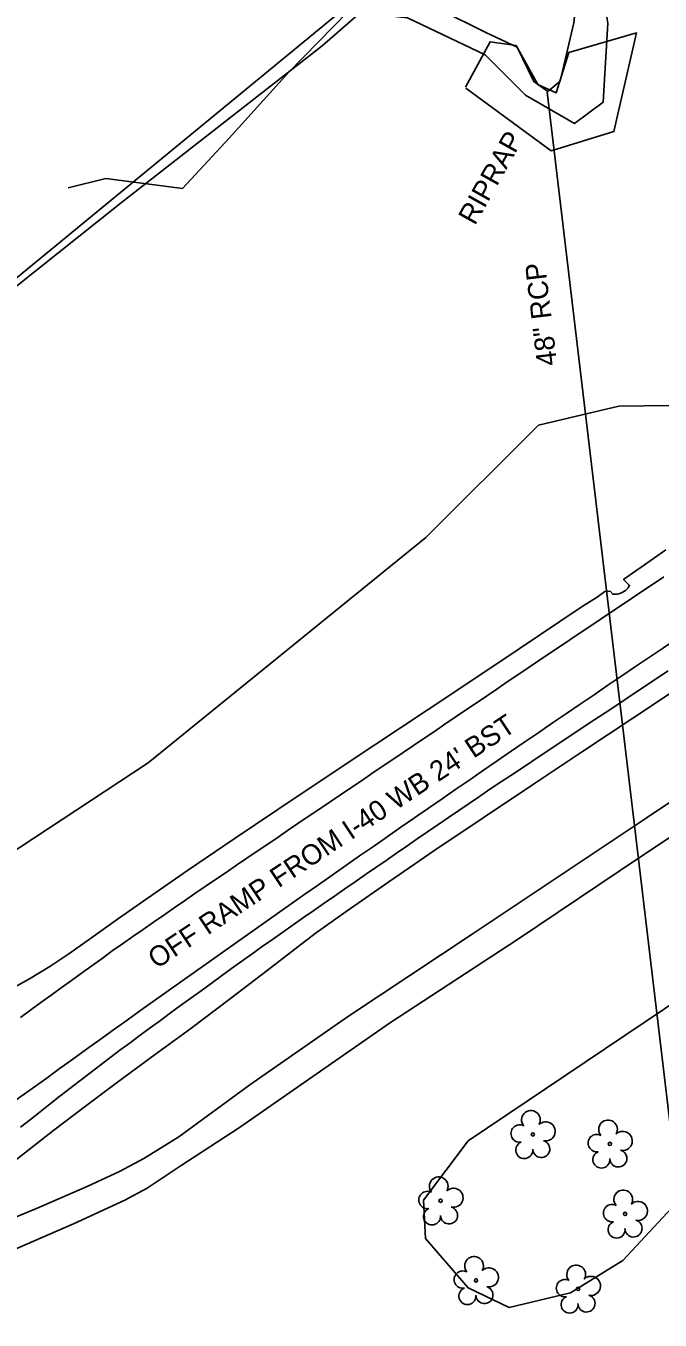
# Model space of a CAD drawing. Extents: x 2074109 to 2077820, y 741079 to 746031.
# Drawn here: x 2075438.5 to 2075564.6, y 743972 to 744229 of the extents above; entities that cross this region are included whole.
import ezdxf

# ---------------------------------------------------------------- set-up
doc = ezdxf.new("R2010")
doc.units = 0
for name, color, linetype in [('Exist Horizontal Alignment', 7, 'Continuous'), ('Exist Hydro Stream or Body of Water', 7, 'Continuous'), ('Exist Other Culture Area Outline', 7, 'Continuous'), ('Exist Other Culture Area Outline Text', 7, 'Continuous'), ('Exist Other Culture Fence Line', 7, 'Continuous'), ('Exist Right of Way Line', 7, 'Continuous'), ('Exist Roads EOP', 7, 'Continuous'), ('Exist Roads EOP Text', 7, 'Continuous'), ('Exist Roads EOT', 7, 'Continuous'), ('Exist Structure Minor Paved Ditch or Gutter', 7, 'Continuous'), ('Exist Structure Minor Pipes RCP 48 Inch', 7, 'Continuous'), ('Exist Structure Minor Pipes RCP 48 Inch Text', 7, 'Continuous'), ('Exist Vegetation Hedge Row', 7, 'Continuous'), ('Exist Vegetation Tree CELL', 7, 'Continuous'), ('Exist Vegetation Woods Line', 7, 'Continuous')]:
    doc.layers.add(name, color=color, linetype=linetype)

msp = doc.modelspace()

# ---------------------------------------------------------------- linework, layer by layer
at = {"layer": 'Exist Horizontal Alignment'}
msp.add_arc((2078143.35, 740278.32), 4614.57, 123.47052, 126.11267, dxfattribs=at)
at = {"layer": 'Exist Hydro Stream or Body of Water'}
msp.add_lwpolyline([(2075544.73, 744283.29), (2075551.12, 744265.56), (2075547.41, 744229.65), (2075544.66, 744218.04), (2075542.23, 744216.03), (2075539.46, 744217.96), (2075536.16, 744224.81), (2075529.92, 744227.74), (2075511.75, 744236.8), (2075501.32, 744236.15), (2075495.85, 744232.06)], dxfattribs=at)
at = {"layer": 'Exist Other Culture Area Outline'}
msp.add_lwpolyline([(2075525.97, 744216.67), (2075542.88, 744204.24), (2075555.36, 744208.06), (2075559.85, 744227.64), (2075546.4, 744223.74), (2075543.91, 744215.76), (2075540.23, 744217.4), (2075535.92, 744225.12), (2075530.78, 744225.9), (2075525.9, 744216.89)], dxfattribs=at)
at = {"layer": 'Exist Other Culture Fence Line'}
msp.add_lwpolyline([(2075690.21, 744385.61), (2075656.34, 744358.38), (2075632.77, 744338.73), (2075611.28, 744320.39), (2075581.11, 744296.73), (2075554.17, 744274.55), (2075497.37, 744225.11), (2075457.53, 744193.95), (2075418.99, 744163.3)], dxfattribs=at)
at = {"layer": 'Exist Right of Way Line'}
msp.add_line((2075289.65, 744058.22), (2075694.31, 744390.69), dxfattribs=at)
at = {"layer": 'Exist Roads EOP'}
for points in [[(2075434.35, 744037.03), (2075439.27, 744039.77), (2075443.28, 744042.2), (2075447.08, 744044.73), (2075451.39, 744047.77), (2075456.96, 744051.71), (2075463.48, 744056.29), (2075470.63, 744061.25), (2075479.91, 744067.58), (2075492.84, 744076.24), (2075507.84, 744086.22), (2075523.34, 744096.52), (2075536.55, 744105.3), (2075544.65, 744110.75), (2075549.26, 744113.85), (2075552.01, 744115.59), (2075553.55, 744116.67), (2075554.62, 744116.78), (2075555.16, 744116.18), (2075555.45, 744116.14), (2075555.74, 744116.13), (2075556.04, 744116.17), (2075556.36, 744116.24), (2075556.68, 744116.35), (2075557, 744116.51), (2075557.34, 744116.7), (2075557.66, 744116.91), (2075557.94, 744117.15), (2075558.17, 744117.4), (2075558.35, 744117.66), (2075558.47, 744117.9), (2075557.28, 744119.09), (2075559.73, 744120.78), (2075560.8, 744121.51), (2075565.71, 744124.93)], [(2075569.19, 744098.24), (2075559.13, 744091.55), (2075549.16, 744084.93), (2075539.16, 744078.3), (2075529.36, 744071.75), (2075519.82, 744065.31), (2075510.65, 744059.03), (2075502.16, 744053.11), (2075496.03, 744048.72), (2075491.98, 744045.64), (2075486.48, 744041.42), (2075479.18, 744035.81), (2075471.31, 744029.91), (2075463.31, 744024.04), (2075456.44, 744019), (2075450.62, 744014.68), (2075444.07, 744009.67), (2075436.71, 744003.91)]]:
    msp.add_lwpolyline(points, dxfattribs=at)
at = {"layer": 'Exist Roads EOT'}
for points in [[(2075565.29, 744119.61), (2075563.22, 744118.22), (2075561.14, 744116.83), (2075559.07, 744115.44), (2075556.99, 744114.05), (2075554.91, 744112.66), (2075552.84, 744111.27), (2075550.76, 744109.88), (2075548.69, 744108.48), (2075546.61, 744107.09), (2075544.53, 744105.7), (2075542.46, 744104.31), (2075540.39, 744102.91), (2075538.32, 744101.51), (2075536.25, 744100.11), (2075534.18, 744098.71), (2075532.11, 744097.31), (2075530.04, 744095.91), (2075527.97, 744094.51), (2075525.9, 744093.11), (2075523.83, 744091.71), (2075521.76, 744090.31), (2075519.69, 744088.91), (2075517.62, 744087.51), (2075515.56, 744086.1), (2075513.49, 744084.7), (2075511.42, 744083.3), (2075509.35, 744081.9), (2075507.28, 744080.51), (2075505.21, 744079.11), (2075503.13, 744077.71), (2075501.06, 744076.31), (2075498.99, 744074.92), (2075496.92, 744073.52), (2075494.85, 744072.12), (2075492.78, 744070.72), (2075490.71, 744069.32), (2075488.65, 744067.91), (2075486.58, 744066.51), (2075484.51, 744065.1), (2075482.44, 744063.7), (2075480.38, 744062.3), (2075478.31, 744060.89), (2075476.24, 744059.49), (2075474.18, 744058.09), (2075472.12, 744056.67), (2075470.06, 744055.25), (2075468.01, 744053.82), (2075465.96, 744052.4), (2075463.9, 744050.98), (2075461.85, 744049.56), (2075459.79, 744048.13), (2075457.74, 744046.71), (2075455.69, 744045.28), (2075453.67, 744043.81), (2075451.64, 744042.35), (2075449.61, 744040.89), (2075447.59, 744039.43), (2075445.56, 744037.97), (2075443.54, 744036.5), (2075441.52, 744035.03), (2075439.5, 744033.56), (2075437.48, 744032.09)], [(2075566.13, 744100.9), (2075564.05, 744099.51), (2075561.97, 744098.13), (2075559.89, 744096.75), (2075557.8, 744095.37), (2075555.72, 744093.99), (2075553.63, 744092.61), (2075551.55, 744091.23), (2075549.47, 744089.85), (2075547.38, 744088.47), (2075545.3, 744087.09), (2075543.22, 744085.71), (2075541.14, 744084.33), (2075539.06, 744082.94), (2075536.98, 744081.55), (2075534.9, 744080.16), (2075532.82, 744078.78), (2075530.74, 744077.39), (2075528.67, 744075.99), (2075526.61, 744074.58), (2075524.54, 744073.17), (2075522.48, 744071.77), (2075520.41, 744070.36), (2075518.35, 744068.95), (2075516.28, 744067.54), (2075514.23, 744066.12), (2075512.17, 744064.7), (2075510.11, 744063.28), (2075508.05, 744061.87), (2075506, 744060.45), (2075503.94, 744059.03), (2075501.88, 744057.61), (2075499.82, 744056.19), (2075497.77, 744054.77), (2075495.72, 744053.34), (2075493.68, 744051.9), (2075491.63, 744050.46), (2075489.59, 744049.03), (2075487.54, 744047.59), (2075485.5, 744046.15), (2075483.47, 744044.7), (2075481.44, 744043.24), (2075479.41, 744041.78), (2075477.39, 744040.31), (2075475.36, 744038.85), (2075473.33, 744037.39), (2075471.31, 744035.93), (2075469.28, 744034.46), (2075467.27, 744032.98), (2075465.26, 744031.5), (2075463.25, 744030.01), (2075461.24, 744028.53), (2075459.22, 744027.05), (2075457.21, 744025.57), (2075455.21, 744024.07), (2075453.23, 744022.55), (2075451.25, 744021.02), (2075449.27, 744019.5), (2075447.29, 744017.97), (2075445.31, 744016.45), (2075443.34, 744014.9), (2075441.38, 744013.36), (2075439.42, 744011.81), (2075437.45, 744010.26)]]:
    msp.add_lwpolyline(points, dxfattribs=at)
at = {"layer": 'Exist Structure Minor Paved Ditch or Gutter'}
for points in [[(2075411.44, 743982.03), (2075426.78, 743988.4), (2075440.62, 743994.15), (2075450.87, 743998.58), (2075457.14, 744001.45), (2075462, 744004.06), (2075468.94, 744008.34), (2075483, 744018.69), (2075502.63, 744032.32), (2075526.98, 744048.51), (2075561.15, 744071.27), (2075587.52, 744088.93), (2075615.92, 744107.9), (2075636.89, 744121.79), (2075661.48, 744139.5), (2075682.6, 744154.69), (2075696.98, 744165.18), (2075715.36, 744178.82), (2075732.36, 744192.27), (2075749.86, 744206.47), (2075766.88, 744221.52)], [(2075773.57, 744219.34), (2075752.88, 744201.9), (2075725.45, 744179.61), (2075705.54, 744164.61), (2075687.22, 744151.12), (2075665.75, 744135.87), (2075649.47, 744123.69), (2075626.61, 744108.29), (2075603.41, 744092.8), (2075580.72, 744077.29), (2075560.42, 744063.88), (2075536.19, 744047.58), (2075510.81, 744030.92), (2075480.97, 744010.24), (2075469.41, 744002.69), (2075462.66, 743998.19), (2075458.19, 743995.77), (2075447.97, 743991.11), (2075432.21, 743984.28), (2075417.58, 743978.24), (2075409.83, 743975.03), (2075406.25, 743974.22)]]:
    msp.add_lwpolyline(points, dxfattribs=at)
at = {"layer": 'Exist Structure Minor Pipes RCP 48 Inch'}
msp.add_line((2075542.08, 744215.86), (2075597.15, 743753.38), dxfattribs=at)
at = {"layer": 'Exist Vegetation Hedge Row'}
msp.add_lwpolyline([(2075819.04, 744199.24), (2075807.13, 744185.86), (2075800.28, 744186.97), (2075778.9, 744168.21), (2075710.95, 744107.9), (2075631.89, 744041.9), (2075571.23, 743998.96), (2075557.13, 743983.79), (2075546.74, 743977.4), (2075534.56, 743974.43), (2075526.41, 743978.39), (2075517.94, 743988.2), (2075517.53, 743995.81), (2075526.39, 744007.57), (2075624.05, 744073.17), (2075705.84, 744137.08), (2075778.11, 744202.94), (2075776.25, 744208.85), (2075779.75, 744216.85)], dxfattribs=at)
at = {"layer": 'Exist Vegetation Tree CELL'}
for p, q in [((2075539.26, 744008.85), (2075539.26, 744008.85)), ((2075554.58, 744006.97), (2075554.58, 744006.97)), ((2075520.94, 743995.67), (2075520.94, 743995.67)), ((2075557.6, 743993.05), (2075557.6, 743993.05)), ((2075527.97, 743979.85), (2075527.97, 743979.85)), ((2075548.26, 743978.16), (2075548.26, 743978.16))]:
    msp.add_line(p, q, dxfattribs=at)
for centre in [(2075539.26, 744008.85), (2075554.58, 744006.97), (2075520.94, 743995.67), (2075557.6, 743993.05), (2075527.97, 743979.85), (2075548.26, 743978.16)]:
    msp.add_circle(centre, 0.326, dxfattribs=at)
for centre, radius, start, end in [((2075538.87, 744011.73), 1.86, 330.1651, 219.7134), ((2075536.65, 744009.01), 1.73, 62.6636, 279.3457), ((2075541.81, 744009.44), 1.9, 257.1011, 134.1999), ((2075554.2, 744009.84), 1.86, 330.1651, 219.7134), ((2075537.55, 744005.73), 1.69, 111.5671, 6.231), ((2075540.93, 744005.95), 1.7, 181.2822, 74.56), ((2075551.97, 744007.12), 1.73, 62.6636, 279.3457), ((2075557.13, 744007.55), 1.9, 257.1011, 134.1999), ((2075552.88, 744003.84), 1.69, 111.5671, 6.231), ((2075556.25, 744004.07), 1.7, 181.2822, 74.56), ((2075520.56, 743998.54), 1.86, 330.1651, 219.7134), ((2075518.33, 743995.82), 1.73, 62.6636, 279.3457), ((2075523.49, 743996.26), 1.9, 257.1011, 134.1999), ((2075557.22, 743995.93), 1.86, 330.1651, 219.7134), ((2075522.61, 743992.77), 1.7, 181.2822, 74.56), ((2075555, 743993.21), 1.73, 62.6636, 279.3457), ((2075560.15, 743993.64), 1.9, 257.1011, 134.1999), ((2075519.24, 743992.55), 1.69, 111.5671, 6.231), ((2075559.27, 743990.16), 1.7, 181.2822, 74.56), ((2075555.9, 743989.93), 1.69, 111.5671, 6.231), ((2075527.59, 743982.72), 1.86, 330.1651, 219.7134), ((2075525.37, 743980), 1.73, 62.6636, 279.3457), ((2075530.52, 743980.44), 1.9, 257.1011, 134.1999), ((2075547.87, 743981.03), 1.86, 330.1651, 219.7134), ((2075545.65, 743978.31), 1.73, 62.6636, 279.3457), ((2075550.81, 743978.75), 1.9, 257.1011, 134.1999), ((2075526.27, 743976.73), 1.69, 111.5671, 6.231), ((2075529.64, 743976.95), 1.7, 181.2822, 74.56), ((2075546.55, 743975.04), 1.69, 111.5671, 6.231), ((2075549.93, 743975.26), 1.7, 181.2822, 74.56)]:
    msp.add_arc(centre, radius, start, end, dxfattribs=at)
at = {"layer": 'Exist Vegetation Woods Line'}
for points in [[(2075680.23, 744252.64), (2075658.01, 744236.93), (2075637.81, 744219.2), (2075616.25, 744204.45), (2075603.67, 744195.04), (2075591.15, 744173.96), (2075576.21, 744153.79), (2075556.35, 744153.49)], [(2075469.64, 744196.76), (2075478.89, 744206.76), (2075490.72, 744219.81), (2075502.55, 744231.89), (2075514.37, 744230.62), (2075529.82, 744223.32), (2075537.82, 744215.3), (2075547.55, 744209.65), (2075553.23, 744213.86), (2075554.19, 744229.57), (2075552.23, 744241.14), (2075535.96, 744239.9), (2075528.63, 744237.52), (2075512.79, 744244.88), (2075504.86, 744245.71)], [(2075446.93, 744196.84), (2075454.4, 744198.71), (2075469.64, 744196.76)], [(2075556.35, 744153.49), (2075540.41, 744149.72), (2075518, 744127.44), (2075462.82, 744082.64), (2075411.72, 744049.01), (2075392.57, 744033.87)]]:
    msp.add_lwpolyline(points, dxfattribs=at)

# ---------------------------------------------------------------- texts
at = {"layer": 'Exist Other Culture Area Outline Text'}
msp.add_text('RIPRAP', height=4, rotation=60.742, dxfattribs=at).set_placement((2075527.73, 744189.25))
at = {"layer": 'Exist Roads EOP Text'}
msp.add_text("OFF RAMP FROM I-40 WB 24' BST", height=4, rotation=33.5919, dxfattribs=at).set_placement((2075464.5, 744041.61))
at = {"layer": 'Exist Structure Minor Pipes RCP 48 Inch Text'}
msp.add_text('48" RCP', height=4, rotation=96.7903, dxfattribs=at).set_placement((2075544.1, 744161.73))

doc.saveas('drawing.dxf')
